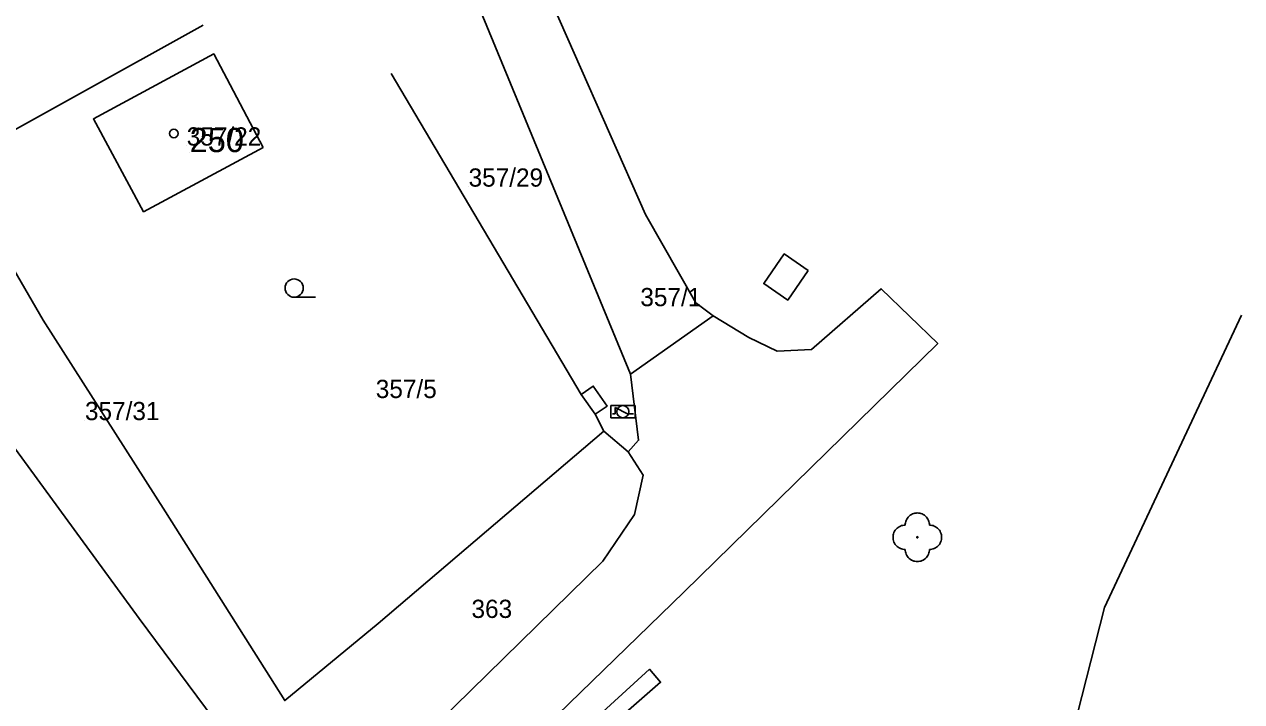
# Model space of a CAD drawing. Extents: x -836568 to -836015, y -1070547 to -1070212.
# Drawn here: x -836491.5 to -836441.4, y -1070276.7 to -1070248.8 of the extents above; entities that cross this region are included whole.
import ezdxf

# ---------------------------------------------------------------- set-up
doc = ezdxf.new("R2010")
doc.units = 0
for name, color, linetype in [('BodPole_mer', 7, 'Continuous'), ('Budovy_hranice', 7, 'Continuous'), ('Budovy_kody', 7, 'Continuous'), ('Doprava_hranice', 7, 'Continuous'), ('OstPloch_hranice', 7, 'Continuous'), ('OstPloch_kody', 7, 'Continuous'), ('PovrZnIS_body', 7, 'Continuous'), ('PovrZnIS_hranice', 7, 'Continuous'), ('RuianAdr_popis', 7, 'Continuous'), ('RuianPar_popis', 7, 'Continuous'), ('Stavby_hr_stav', 7, 'Continuous'), ('Stavby_linie', 7, 'Continuous'), ('Vodstvo_hranice', 7, 'Continuous'), ('Zelen_body', 7, 'Continuous')]:
    doc.layers.add(name, color=color, linetype=linetype)

msp = doc.modelspace()

# ---------------------------------------------------------------- linework, layer by layer
at = {"layer": 'BodPole_mer'}
for p, q in [((-836481.66, -1070253.86), (-836481.66, -1070253.86)), ((-836486.58, -1070256.5), (-836486.58, -1070256.5)), ((-836463.85, -1070260.25), (-836463.85, -1070260.25)), ((-836460.06, -1070260.14), (-836460.06, -1070260.14)), ((-836463.13, -1070260.78), (-836463.13, -1070260.78)), ((-836490.71, -1070260.96), (-836490.71, -1070260.96)), ((-836461.66, -1070261.68), (-836461.66, -1070261.68)), ((-836460.5, -1070262.24), (-836460.5, -1070262.24)), ((-836459.09, -1070262.17), (-836459.09, -1070262.17)), ((-836466.54, -1070263.19), (-836466.54, -1070263.19)), ((-836468.07, -1070263.68), (-836468.07, -1070263.68)), ((-836468.56, -1070264.02), (-836468.56, -1070264.02)), ((-836467.99, -1070264.84), (-836467.99, -1070264.84)), ((-836467.5, -1070264.5), (-836467.5, -1070264.5)), ((-836466.85, -1070264.73), (-836466.85, -1070264.73)), ((-836467.63, -1070265.54), (-836467.63, -1070265.54)), ((-836466.2, -1070265.91), (-836466.2, -1070265.91)), ((-836466.63, -1070266.39), (-836466.63, -1070266.39)), ((-836466.02, -1070267.34), (-836466.02, -1070267.34)), ((-836485.67, -1070268.85), (-836485.67, -1070268.85)), ((-836466.37, -1070268.96), (-836466.37, -1070268.96)), ((-836454.73, -1070269.9), (-836454.73, -1070269.9)), ((-836467.68, -1070270.88), (-836467.68, -1070270.88)), ((-836464.34, -1070272.16), (-836464.34, -1070272.16)), ((-836447.03, -1070272.79), (-836447.03, -1070272.79)), ((-836486.76, -1070273.24), (-836486.76, -1070273.24)), ((-836476.92, -1070273.45), (-836476.92, -1070273.45)), ((-836465.76, -1070275.33), (-836465.76, -1070275.33)), ((-836465.3, -1070275.87), (-836465.3, -1070275.87)), ((-836480.77, -1070276.62), (-836480.77, -1070276.62))]:
    msp.add_line(p, q, dxfattribs=at)
at = {"layer": 'Budovy_hranice'}
msp.add_lwpolyline([(-836481.66, -1070253.86), (-836486.58, -1070256.5), (-836488.64, -1070252.68), (-836483.69, -1070250.01), (-836481.66, -1070253.86)], dxfattribs=at)
at = {"layer": 'Budovy_kody'}
msp.add_circle((-836485.33, -1070253.28), 0.175, dxfattribs=at)
at = {"layer": 'Doprava_hranice'}
for points in [[(-836565.55, -1070255.75), (-836568.29, -1070246.94), (-836565.3, -1070243.45), (-836558.59, -1070239.29), (-836553.32, -1070234.26), (-836550.36, -1070230.73), (-836544.63, -1070222.38), (-836541.42, -1070218.21), (-836539.02, -1070215.95), (-836535.5, -1070213.99), (-836517.48, -1070213.29), (-836497.22, -1070212.11), (-836494.05, -1070212.5), (-836489.39, -1070214.02), (-836485.93, -1070216.36), (-836482.28, -1070220.4), (-836478.23, -1070227.56), (-836471.79, -1070243.33), (-836465.92, -1070256.62), (-836463.85, -1070260.25), (-836463.13, -1070260.78)], [(-836466.54, -1070263.19), (-836474.56, -1070243.73), (-836478.12, -1070235.21), (-836483.33, -1070224.14), (-836486.58, -1070219.75), (-836489.27, -1070217.57), (-836492.22, -1070215.97), (-836495.08, -1070215.2), (-836498.82, -1070214.84), (-836513.64, -1070215.7), (-836532.05, -1070216.8), (-836534.5, -1070217.36), (-836537.57, -1070219.18), (-836540.24, -1070221.43), (-836545, -1070227.8), (-836549.52, -1070233.43), (-836552.32, -1070236.92), (-836557.98, -1070243.27), (-836562.8, -1070249.08), (-836563.01, -1070249.54), (-836561.48, -1070254.69), (-836565.55, -1070255.75)], [(-836463.13, -1070260.78), (-836461.66, -1070261.68), (-836460.5, -1070262.24), (-836459.09, -1070262.17), (-836456.22, -1070259.67), (-836453.89, -1070261.93), (-836464.34, -1070272.16), (-836473.79, -1070281.33)], [(-836463.13, -1070260.78), (-836466.54, -1070263.19), (-836466.2, -1070265.91), (-836466.63, -1070266.39), (-836466.02, -1070267.34), (-836466.37, -1070268.96), (-836467.68, -1070270.88), (-836477.85, -1070280.85), (-836486.39, -1070290.44)]]:
    msp.add_lwpolyline(points, dxfattribs=at)
at = {"layer": 'OstPloch_hranice'}
msp.add_line((-836467.63, -1070265.54), (-836466.63, -1070266.39), dxfattribs=at)
for points in [[(-836459.22, -1070258.92), (-836460.06, -1070260.14), (-836461.05, -1070259.46), (-836460.21, -1070258.24), (-836459.22, -1070258.92)], [(-836464.81, -1070325.47), (-836465.74, -1070321.03), (-836464.89, -1070314.87), (-836461.62, -1070306.74), (-836456.41, -1070297.54), (-836450.95, -1070288.2), (-836447.03, -1070272.79), (-836441.38, -1070260.76)]]:
    msp.add_lwpolyline(points, dxfattribs=at)
at = {"layer": 'OstPloch_kody'}
msp.add_line((-836479.505, -1070260.02), (-836480.38, -1070260.02), dxfattribs=at)
msp.add_ellipse((-836480.38, -1070259.645), major_axis=(0.375, 0), ratio=0.999999, dxfattribs=at)
at = {"layer": 'PovrZnIS_body'}
for p, q in [((-836467.35, -1070264.98), (-836467.35, -1070264.48)), ((-836467.35, -1070264.48), (-836466.35, -1070264.48)), ((-836467.271, -1070264.814), (-836467.161, -1070264.814)), ((-836467.161, -1070264.814), (-836467.161, -1070264.564)), ((-836467.161, -1070264.564), (-836466.661, -1070264.814)), ((-836466.661, -1070264.814), (-836466.416, -1070264.814)), ((-836466.35, -1070264.48), (-836466.35, -1070264.98)), ((-836466.35, -1070264.98), (-836467.35, -1070264.98))]:
    msp.add_line(p, q, dxfattribs=at)
msp.add_circle((-836466.85, -1070264.73), 0.25, dxfattribs=at)
at = {"layer": 'PovrZnIS_hranice'}
msp.add_lwpolyline([(-836467.99, -1070264.84), (-836467.5, -1070264.5), (-836468.07, -1070263.68), (-836468.56, -1070264.02), (-836467.99, -1070264.84)], dxfattribs=at)
at = {"layer": 'RuianAdr_popis'}
msp.add_line((-836484.68, -1070254.05), (-836484.68, -1070254.05), dxfattribs=at)
at = {"layer": 'RuianPar_popis'}
for p, q in [((-836484.8, -1070253.78), (-836484.8, -1070253.78)), ((-836473.2, -1070255.47), (-836473.2, -1070255.47)), ((-836466.13, -1070260.39), (-836466.13, -1070260.39)), ((-836477.02, -1070264.17), (-836477.02, -1070264.17)), ((-836488.99, -1070265.08), (-836488.99, -1070265.08)), ((-836473.08, -1070273.22), (-836473.08, -1070273.22))]:
    msp.add_line(p, q, dxfattribs=at)
at = {"layer": 'Stavby_hr_stav'}
msp.add_lwpolyline([(-836475.41, -1070284.71), (-836465.3, -1070275.87), (-836465.76, -1070275.33), (-836475.69, -1070284.41)], dxfattribs=at)
at = {"layer": 'Stavby_linie'}
msp.add_line((-836476.39, -1070250.81), (-836468.56, -1070264.02), dxfattribs=at)
for points in [[(-836484.13, -1070248.82), (-836494.44, -1070254.55), (-836490.71, -1070260.96)], [(-836490.71, -1070260.96), (-836485.67, -1070268.85), (-836480.77, -1070276.62), (-836476.92, -1070273.45)], [(-836476.92, -1070273.45), (-836467.63, -1070265.54), (-836467.99, -1070264.84), (-836468.56, -1070264.02)]]:
    msp.add_lwpolyline(points, dxfattribs=at)
at = {"layer": 'Vodstvo_hranice'}
msp.add_lwpolyline([(-836525.34, -1070271.43), (-836521.88, -1070269.71), (-836516.37, -1070264.96), (-836510.93, -1070262.08), (-836507.11, -1070259.33), (-836503.08, -1070256.96), (-836500.52, -1070256.76), (-836498.86, -1070256.68), (-836495.87, -1070257.41), (-836493.93, -1070263.56), (-836492.75, -1070265.06), (-836486.76, -1070273.24), (-836482.01, -1070279.63), (-836483.74, -1070282.01), (-836486.21, -1070283.75)], dxfattribs=at)
at = {"layer": 'Zelen_body'}
msp.add_line((-836454.73, -1070269.9), (-836454.73, -1070269.9), dxfattribs=at)
for points in [[(-836455.23, -1070269.4), (-836455.228, -1070269.352), (-836455.22, -1070269.303), (-836455.208, -1070269.253), (-836455.19, -1070269.204), (-836455.166, -1070269.155), (-836455.137, -1070269.109), (-836455.103, -1070269.066), (-836455.064, -1070269.027), (-836455.021, -1070268.993), (-836454.975, -1070268.964), (-836454.926, -1070268.94), (-836454.877, -1070268.922), (-836454.827, -1070268.91), (-836454.778, -1070268.902), (-836454.73, -1070268.9), (-836454.682, -1070268.902), (-836454.633, -1070268.91), (-836454.583, -1070268.922), (-836454.534, -1070268.94), (-836454.485, -1070268.964), (-836454.439, -1070268.993), (-836454.396, -1070269.027), (-836454.357, -1070269.066), (-836454.323, -1070269.109), (-836454.294, -1070269.155), (-836454.27, -1070269.204), (-836454.252, -1070269.253), (-836454.24, -1070269.303), (-836454.232, -1070269.352), (-836454.23, -1070269.4)], [(-836455.23, -1070270.4), (-836455.278, -1070270.398), (-836455.327, -1070270.39), (-836455.377, -1070270.378), (-836455.426, -1070270.36), (-836455.475, -1070270.336), (-836455.521, -1070270.307), (-836455.564, -1070270.273), (-836455.603, -1070270.234), (-836455.637, -1070270.191), (-836455.666, -1070270.145), (-836455.69, -1070270.096), (-836455.708, -1070270.047), (-836455.72, -1070269.997), (-836455.728, -1070269.948), (-836455.73, -1070269.9), (-836455.728, -1070269.852), (-836455.72, -1070269.803), (-836455.708, -1070269.753), (-836455.69, -1070269.704), (-836455.666, -1070269.655), (-836455.637, -1070269.609), (-836455.603, -1070269.566), (-836455.564, -1070269.527), (-836455.521, -1070269.493), (-836455.475, -1070269.464), (-836455.426, -1070269.44), (-836455.377, -1070269.422), (-836455.327, -1070269.41), (-836455.278, -1070269.402), (-836455.23, -1070269.4)], [(-836454.23, -1070269.4), (-836454.182, -1070269.402), (-836454.133, -1070269.41), (-836454.083, -1070269.422), (-836454.034, -1070269.44), (-836453.985, -1070269.464), (-836453.939, -1070269.493), (-836453.896, -1070269.527), (-836453.857, -1070269.566), (-836453.823, -1070269.609), (-836453.794, -1070269.655), (-836453.77, -1070269.704), (-836453.752, -1070269.753), (-836453.74, -1070269.803), (-836453.732, -1070269.852), (-836453.73, -1070269.9), (-836453.732, -1070269.948), (-836453.74, -1070269.997), (-836453.752, -1070270.047), (-836453.77, -1070270.096), (-836453.794, -1070270.145), (-836453.823, -1070270.191), (-836453.857, -1070270.234), (-836453.896, -1070270.273), (-836453.939, -1070270.307), (-836453.985, -1070270.336), (-836454.034, -1070270.36), (-836454.083, -1070270.378), (-836454.133, -1070270.39), (-836454.182, -1070270.398), (-836454.23, -1070270.4)], [(-836454.23, -1070270.4), (-836454.232, -1070270.448), (-836454.24, -1070270.497), (-836454.252, -1070270.547), (-836454.27, -1070270.596), (-836454.294, -1070270.645), (-836454.323, -1070270.691), (-836454.357, -1070270.734), (-836454.396, -1070270.773), (-836454.439, -1070270.807), (-836454.485, -1070270.836), (-836454.534, -1070270.86), (-836454.583, -1070270.878), (-836454.633, -1070270.89), (-836454.682, -1070270.898), (-836454.73, -1070270.9), (-836454.778, -1070270.898), (-836454.827, -1070270.89), (-836454.877, -1070270.878), (-836454.926, -1070270.86), (-836454.975, -1070270.836), (-836455.021, -1070270.807), (-836455.064, -1070270.773), (-836455.103, -1070270.734), (-836455.137, -1070270.691), (-836455.166, -1070270.645), (-836455.19, -1070270.596), (-836455.208, -1070270.547), (-836455.22, -1070270.497), (-836455.228, -1070270.448), (-836455.23, -1070270.4)]]:
    msp.add_lwpolyline(points, dxfattribs=at)
msp.add_ellipse((-836454.73, -1070269.9), major_axis=(0.025, 0), ratio=0.999997, dxfattribs=at)

# ---------------------------------------------------------------- texts
at = {"layer": 'RuianAdr_popis'}
msp.add_text('250', height=1, dxfattribs=at).set_placement((-836484.68, -1070254.05))
at = {"layer": 'RuianPar_popis'}
for s, p in [('357/22', (-836484.8, -1070253.78)), ('357/29', (-836473.2, -1070255.47)), ('357/1', (-836466.13, -1070260.39)), ('357/5', (-836477.02, -1070264.17)), ('357/31', (-836488.99, -1070265.08)), ('363', (-836473.08, -1070273.22))]:
    msp.add_text(s, height=0.75, dxfattribs=at).set_placement(p)

doc.saveas('drawing.dxf')
